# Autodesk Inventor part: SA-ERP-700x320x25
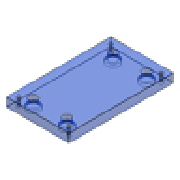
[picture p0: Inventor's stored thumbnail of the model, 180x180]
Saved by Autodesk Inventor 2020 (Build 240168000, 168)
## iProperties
Created: 2019-01
Part Number: SA-ERP-700x320x25
Material: S 55 C
Description: Ejector Retainer Plate
Document SubType Name: Modeling
Designer: LENOVO-CADCIM
Standard Revision: 1
Manufacturer: FUTABA
Language: en-US
Size Designation: 700x320x25
Categories: <MemberInstance><Categories><Category DisplayName="Mold" InternalName="349578f2-f4d4-4954-8c09-8e99297a61c0" Mnemonic="MOLD"><Category DisplayName="Mold Plates"
Density: 7.85 g/cm^3
Appearance: Clear - Blue
IsCustomPart: 1
Author: LENOVO-CADCIM
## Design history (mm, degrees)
sketch "Sketch1"
  geometry: L1 (-160, 350)-(160, 350); L2 (160, 350)-(160, -350); L3 (160, -350)-(-160, -350); L4 (-160, -350)-(-160, 350); 5 further points
  constraints: 8 end point, 2 midpoint, 2 parallel, 1 horizontal, 1 horizontal alignment, 1 perpendicular, 1 vertical alignment
  dimensions: "d84" = 320 distance between parallel lines of L2 L4 (= W_); "d85" = 700 distance between parallel lines of L3 L1 (= L); "d86" = 147 horizontal distance of point (0, 0) point (-147, 337) (= 0.5 x S2_W); "d87" = 337 vertical distance of point (0, 0) point (-147, 337) (= 0.5 x S2_L); "d88" = 128 horizontal distance of point (0, 0) point (-128, 317) (= 0.5 x RP_W); "d89" = 317 vertical distance of point (0, 0) point (-128, 317) (= 0.5 x RP_L)
extrude "Extrusion1" new body sketch "Sketch1" distance "d20" = 25 (= H_); taper "d30" = 0 deg
body "Solid1"
hole "Hole1" sketch "Sketch1" diameter "d90" = 10.106; stored, may be unused: countersink angle "d94" = 90 deg, drill point angle "d96" = 0 deg; dims "d91" = 6, "d92" = 4, "d93" = 2, "d95" = 25 (= H_)
pattern_linear "Rectangular Pattern1" dims "d99" = 674 (computed from S2_L, Nl), "d102" = 294 (computed from S2_W, Nw)
hole "Hole2" sketch "Sketch1" diameter "d103" = 30 (= RP_d1); stored, may be unused: countersink angle "d107" = 90 deg, drill point angle "d109" = 0 deg; dims "d104" = 6, "d105" = 36 (= RP_d2), "d106" = 4 (= RP_k), "d108" = 25 (= H_)
pattern_linear "Rectangular Pattern2" dims "d112" = 634 (computed from RP_L, Nl), "d115" = 256 (computed from RP_W, Nw)
chamfer "Chamfer1" distance "d116" = 0.5; stored, may be unused: second distance "d117" = 2, angle "d118" = 45 deg
other parameters: "L" = 700 [user parameter; used in 1 equation term], "W_" = 320 [user parameter; used in 1 equation term], "H_" = 25 [user parameter; used in 3 equation terms], "S2_W" = 294 [user parameter; used in 2 equation terms], "S2_L" = 674 [user parameter; used in 2 equation terms], "RP_k" = 4 [user parameter; used in 1 equation term], "RP_d1" = 30 [user parameter; used in 1 equation term], "RP_d2" = 36 [user parameter; used in 1 equation term], "RP_L" = 634 [user parameter; used in 2 equation terms], "RP_W" = 256 [user parameter; used in 2 equation terms]
